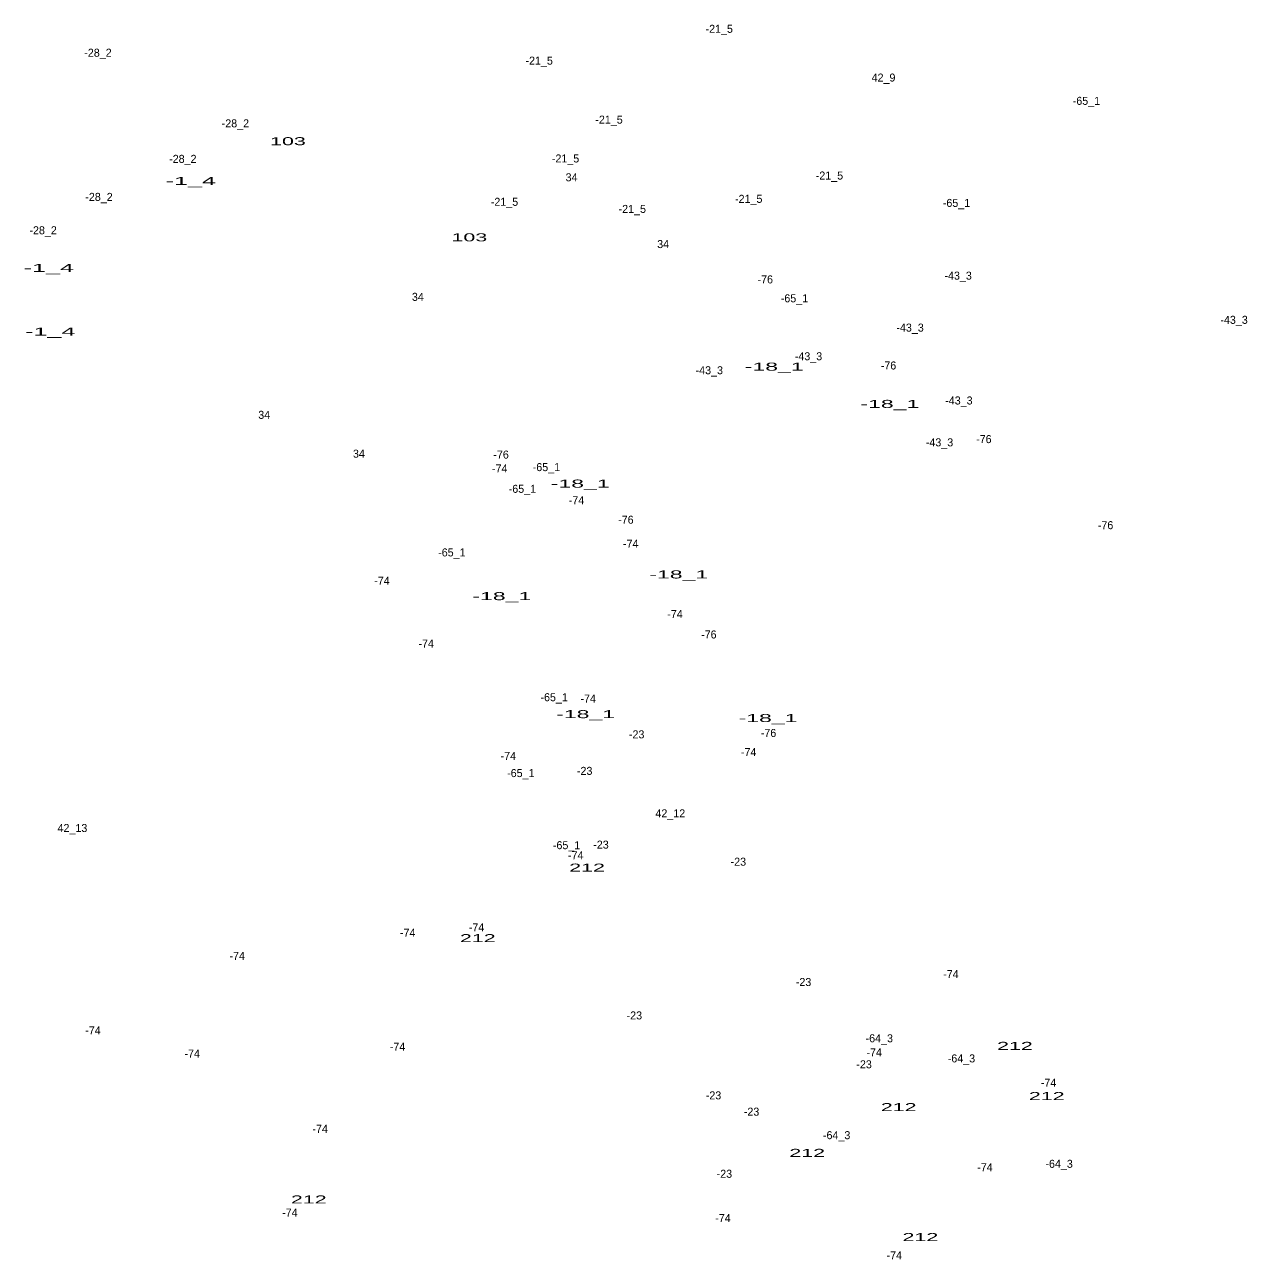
# Model space of a CAD drawing. Extents: x -656096 to -652763, y -1002270 to -998958.
# Drawn here: x -654063 to -653452, y -1000982 to -1000365 of the extents above; entities that cross this region are included whole.
import ezdxf
from ezdxf.enums import TextEntityAlignment as Align

# ---------------------------------------------------------------- set-up
doc = ezdxf.new("R2010")
doc.units = 0
doc.header["$LTSCALE"] = 1.6
doc.layers.add('24', color=7, linetype='Continuous')

msp = doc.modelspace()

# ---------------------------------------------------------------- texts
at = {"layer": '24'}
for s, p in [('-21_5', (-653715.666, -1000369.18)), ('-28_2', (-654026.032, -1000381.13)), ('-21_5', (-653805.626, -1000385.08)), ('42_9', (-653633.594, -1000393.54)), ('-65_1', (-653532.232, -1000405.17)), ('-28_2', (-653957.392, -1000416.42)), ('-21_5', (-653770.726, -1000414.56)), ('-28_2', (-653983.642, -1000434.15)), ('-21_5', (-653792.446, -1000433.96)), ('-21_5', (-653660.616, -1000442.49)), ('34', (-653789.451, -1000443.37)), ('-28_2', (-654025.522, -1000453.16)), ('-21_5', (-653700.936, -1000454.13)), ('-21_5', (-653822.956, -1000455.62)), ('-21_5', (-653759.096, -1000459.17)), ('-65_1', (-653597.132, -1000456.17)), ('-28_2', (-654053.442, -1000469.83)), ('34', (-653743.691, -1000476.73)), ('-43_3', (-653596.317, -1000492.5)), ('-76', (-653692.675, -1000494.38)), ('34', (-653866.221, -1000503.1)), ('-65_1', (-653678.072, -1000503.82)), ('-43_3', (-653458.457, -1000514.59)), ('-43_3', (-653620.327, -1000518.46)), ('-43_3', (-653671.067, -1000532.79)), ('-43_3', (-653720.637, -1000539.77)), ('-76', (-653631.105, -1000537.39)), ('-43_3', (-653595.937, -1000554.88)), ('34', (-653942.991, -1000562.06)), ('-43_3', (-653605.617, -1000575.8)), ('-76', (-653583.465, -1000574.19)), ('34', (-653895.681, -1000581.45)), ('-76', (-653824.655, -1000581.92)), ('-74', (-653825.325, -1000588.84)), ('-65_1', (-653802.002, -1000588.18)), ('-65_1', (-653814.002, -1000599.02)), ('-74', (-653786.985, -1000604.72)), ('-76', (-653762.305, -1000614.46)), ('-76', (-653522.665, -1000617.19)), ('-74', (-653759.875, -1000626.42)), ('-65_1', (-653849.242, -1000630.79)), ('-74', (-653884.155, -1000644.94)), ('-74', (-653737.765, -1000661.59)), ('-74', (-653862.075, -1000676.32)), ('-76', (-653720.865, -1000671.8)), ('-65_1', (-653798.132, -1000703.15)), ('-74', (-653781.145, -1000703.82)), ('-23', (-653756.915, -1000721.71)), ('-76', (-653691.045, -1000721)), ('-74', (-653821.035, -1000732.49)), ('-74', (-653700.975, -1000730.56)), ('-65_1', (-653814.782, -1000741.04)), ('-23', (-653782.895, -1000739.94)), ('42_12', (-653740.113, -1000761.17)), ('42_13', (-654038.803, -1000768.5)), ('-65_1', (-653791.932, -1000777.07)), ('-74', (-653787.345, -1000782.08)), ('-23', (-653774.745, -1000776.79)), ('-23', (-653706.115, -1000785.33)), ('-74', (-653836.905, -1000818.11)), ('-74', (-653871.295, -1000820.78)), ('-74', (-653956.495, -1000832.41)), ('-74', (-653599.935, -1000841.5)), ('-23', (-653673.545, -1000845.45)), ('-23', (-653758.075, -1000862.13)), ('-74', (-654028.525, -1000869.6)), ('-64_3', (-653635.712, -1000873.55)), ('-74', (-653876.405, -1000877.77)), ('-74', (-653638.275, -1000880.62)), ('-74', (-653978.955, -1000881.22)), ('-23', (-653643.305, -1000886.56)), ('-64_3', (-653594.662, -1000883.61)), ('-74', (-653551.145, -1000895.73)), ('-23', (-653718.525, -1000902.08)), ('-23', (-653699.525, -1000910.22)), ('-74', (-653915.055, -1000918.8)), ('-64_3', (-653657.012, -1000921.97)), ('-64_3', (-653545.872, -1000936.27)), ('-23', (-653713.095, -1000941.25)), ('-74', (-653582.895, -1000937.96)), ('-74', (-653930.165, -1000960.64)), ('-74', (-653713.795, -1000963.39)), ('-74', (-653628.205, -1000981.99))]:
    msp.add_text(s, height=4, dxfattribs=at).set_placement(p, align=Align.CENTER)
for s, width, p in [('103', 2, (-653931.124, -1000425.33)), ('-1_4', 2.35, (-653979.677, -1000445.21)), ('103', 2, (-653840.504, -1000473.37)), ('-1_4', 2.35, (-654050.627, -1000488.65)), ('-1_4', 2.35, (-654049.857, -1000520.46)), ('-18_1', 2.15, (-653688.197, -1000537.98)), ('-18_1', 2.15, (-653630.427, -1000556.6)), ('-18_1', 2.15, (-653785.127, -1000596.41)), ('-18_1', 2.15, (-653735.887, -1000641.79)), ('-18_1', 2.15, (-653824.287, -1000652.65)), ('-18_1', 2.15, (-653782.417, -1000711.61)), ('-18_1', 2.15, (-653691.297, -1000713.55)), ('212', 2, (-653781.697, -1000788.28)), ('212', 2, (-653836.307, -1000823.53)), ('212', 2, (-653567.927, -1000877.35)), ('212', 2, (-653552.047, -1000902.42)), ('212', 2, (-653626.017, -1000907.95)), ('212', 2, (-653671.717, -1000930.81)), ('212', 2, (-653920.727, -1000954.09)), ('212', 2, (-653615.177, -1000972.87))]:
    msp.add_text(s, height=4, dxfattribs=dict(at, width=width)).set_placement(p, align=Align.CENTER)

doc.saveas('drawing.dxf')
